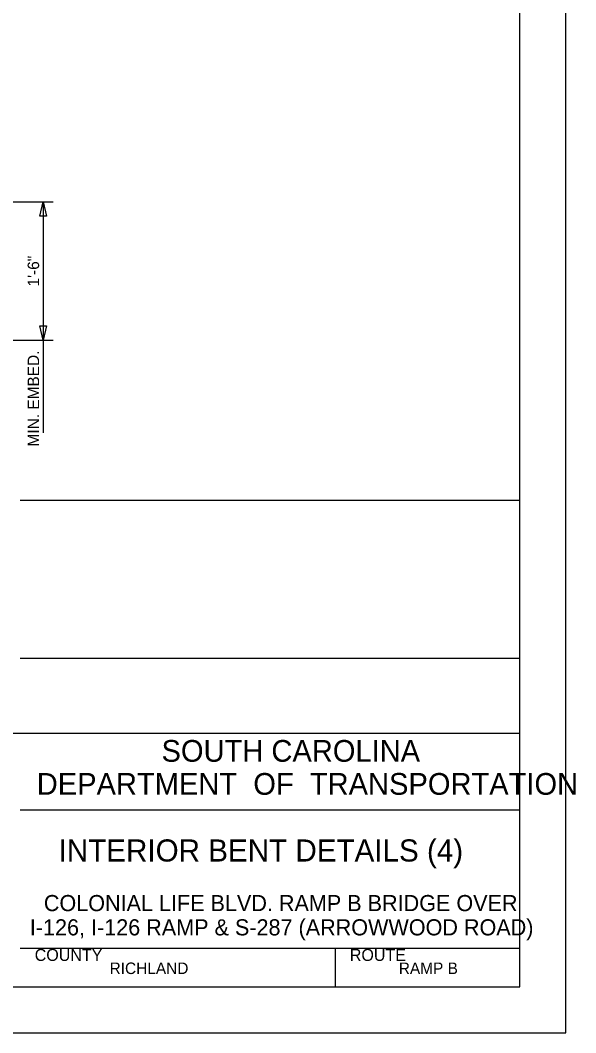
# Model space of a CAD drawing. Extents: x 1970675.2 to 1970711.3, y 796145.2 to 796167.2.
# Drawn here: x 1970705.32 to 1970711.34, y 796145.25 to 796156.23 of the extents above; entities that cross this region are included whole.
import ezdxf

# ---------------------------------------------------------------- set-up
doc = ezdxf.new("R2010")
doc.units = 0
for name, color, linetype in [('BR_AUTO DIMENSION', 7, 'Continuous'), ('BR_BORDER LINES', 7, 'Continuous'), ('BR_TEXT', 7, 'Continuous'), ('Level 31', 7, 'Continuous')]:
    doc.layers.add(name, color=color, linetype=linetype)

msp = doc.modelspace()

# ---------------------------------------------------------------- linework, layer by layer
at = {"layer": 'BR_AUTO DIMENSION'}
for p, q in [((1970704.051, 796154.256), (1970705.675, 796154.256)), ((1970705.569, 796154.256), (1970705.569, 796151.752)), ((1970703.753, 796152.756), (1970705.675, 796152.756))]:
    msp.add_line(p, q, dxfattribs=at)
for points in [[(1970705.533, 796154.1), (1970705.569, 796154.256), (1970705.605, 796154.1)], [(1970705.605, 796152.912), (1970705.569, 796152.756), (1970705.533, 796152.912)]]:
    msp.add_lwpolyline(points, close=True, dxfattribs=at)
at = {"layer": 'BR_BORDER LINES'}
for p, q in [((1970710.736, 796145.746), (1970710.736, 796166.746)), ((1970705.319, 796151.023), (1970710.736, 796151.023)), ((1970705.319, 796149.308), (1970710.736, 796149.308)), ((1970703.236, 796148.496), (1970710.736, 796148.496)), ((1970705.319, 796147.663), (1970710.736, 796147.663)), ((1970705.319, 796146.163), (1970710.736, 796146.163)), ((1970705.417, 796146.163), (1970710.736, 796146.163)), ((1970708.736, 796145.746), (1970708.736, 796146.163)), ((1970677.07, 796145.746), (1970710.736, 796145.746))]:
    msp.add_line(p, q, dxfattribs=at)
at = {"layer": 'Level 31'}
msp.add_line((1970708.028, 796147.223), (1970708.028, 796147.223), dxfattribs=at)
msp.add_lwpolyline([(1970675.236, 796145.246), (1970711.236, 796145.246), (1970711.236, 796167.246), (1970675.236, 796167.246)], close=True, dxfattribs=at)

# ---------------------------------------------------------------- texts
at = {"layer": 'BR_AUTO DIMENSION'}
for s, p in [('1\'-6"', (1970705.524, 796153.339)), ('MIN. EMBED.', (1970705.524, 796151.604))]:
    msp.add_text(s, height=0.125, rotation=90, dxfattribs=at).set_placement(p)
at = {"layer": 'BR_TEXT'}
for s, height, p in [('SOUTH CAROLINA', 0.23587, (1970706.851, 796148.185)), ('DEPARTMENT  OF  TRANSPORTATION', 0.23587, (1970705.498, 796147.827)), ('INTERIOR BENT DETAILS (4)', 0.24, (1970705.735, 796147.103)), ('COLONIAL LIFE BLVD. RAMP B BRIDGE OVER', 0.175, (1970705.575, 796146.565)), ('I-126, I-126 RAMP & S-287 (ARROWWOOD ROAD) ', 0.175, (1970705.423, 796146.302)), ('COUNTY', 0.13, (1970705.476, 796146.025)), ('ROUTE', 0.13, (1970708.893, 796146.025)), ('RICHLAND', 0.125, (1970706.288, 796145.883)), ('RAMP B', 0.125, (1970709.424, 796145.883))]:
    msp.add_text(s, height=height, dxfattribs=at).set_placement(p)

doc.saveas('drawing.dxf')
